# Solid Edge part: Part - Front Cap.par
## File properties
Author: hhakima
Template: Normal.par
Last saved by: hhakima
Revision: 21
Application: Solid Edge
Density: 2712.000 kg/m^3
Accuracy: 0.990
Material: Aluminum, 6061-T6
Face Style: Aluminum
Fill Style: ANSI38(Aluminum)
Virtual Style: Polished aluminum
Coef. of Thermal Exp: 2.3e-05
Thermal Conductivity: 180.0
Specific Heat: 920.0
Modulus of Elasticity: 68947570000.0
Poission's Ratio: 0.33
Yield Stress: 275790280.0
Ultimate Stress: 310264065.0
Elongation: 0.0
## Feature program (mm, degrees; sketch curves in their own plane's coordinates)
sketch for "unnamed Protrusion 1" plane through (0, 0, 0) normal (0, -1, 0) x-axis (1, 0, 0)
  line (42.2517, 30.6615) -> (98.2517, 30.6615)
  line (98.2517, 30.6615) -> (98.2517, 67.6615)
  line (98.2517, 67.6615) -> (42.2517, 67.6615)
  line (42.2517, 67.6615) -> (42.2517, 30.6615)
extrude "unnamed Protrusion 1" add finite 2 along +normal
sketch for "ExtrudedProtrusion_2" #1 plane through (63.7517, -2, 49.1615) normal (0, -1, 0) x-axis (1, 0, 0)
  line (-21.5, -13.5) -> (-21.5, -18.5)
  line (-21.5, -18.5) -> (-26.5, -18.5)
  line (-26.5, -18.5) -> (-26.5, -13.5)
  line (-26.5, -13.5) -> (-21.5, -13.5)
sketch for "ExtrudedProtrusion_2" #2 plane through (63.7517, -2, 49.1615) normal (0, -1, 0) x-axis (1, 0, 0)
  line (34.5, -13.5) -> (34.5, -18.5)
  line (34.5, -18.5) -> (39.5, -18.5)
  line (39.5, -18.5) -> (39.5, -13.5)
  line (39.5, -13.5) -> (34.5, -13.5)
sketch for "ExtrudedProtrusion_2" #3 plane through (63.7517, -2, 49.1615) normal (0, -1, 0) x-axis (1, 0, 0)
sketch for "ExtrudedProtrusion_2" #4 plane through (63.7517, -2, 49.1615) normal (0, -1, 0) x-axis (1, 0, 0)
  line (24.5, 18.5) -> (29.5, 18.5)
  line (29.5, 18.5) -> (29.5, 23.5)
  line (29.5, 23.5) -> (24.5, 23.5)
  line (24.5, 23.5) -> (24.5, 18.5)
  dimension (linear) = 24.5
extrude "ExtrudedProtrusion_2" add finite 2 along -normal
sketch for "Hole_1" plane through (63.7517, -2, 49.1615) normal (0, -1, 0) x-axis (1, 0, 0)
  hole centre (27, 21) bore radius 1.1
hole "Hole_1" diameter 2.2 through
sketch for "unnamed Hole 1" plane through (63.7517, -2, 49.1615) normal (0, -1, 0) x-axis (1, 0, 0)
  hole centre (37, -16) bore radius 1.1
hole "unnamed Hole 1" through
sketch for "unnamed Hole 2" plane through (63.7517, -2, 49.1615) normal (0, -1, 0) x-axis (1, 0, 0)
  hole centre (-24, -16) bore radius 1.1
  dimension (linear) = 24
  dimension (linear) = 24
hole "unnamed Hole 2" through
sketch for "unnamed Hole 3" plane through (63.7517, -2, 49.1615) normal (0, -1, 0) x-axis (1, 0, 0)
hole "unnamed Hole 3" through
pattern "unnamed Pattern 1" of "Hole_1", "unnamed Hole 1", "unnamed Hole 2", "unnamed Hole 3"
sketch for "ExtrudedCutout_1" plane through (69.2517, -2, 49.1615) normal (0, -1, 0) x-axis (1, 0, 0)
  circle centre (-7.5, 4) radius 3.5
  dimension (linear) = 7.5
  dimension (linear) = 7.5
extrude "ExtrudedCutout_1" cut finite 5 along -normal
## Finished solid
Body 1: solid body, 23 faces, 58 edges, 32 vertices.
  Faces by surface: plane 18, cylinder 5
  Edges by curve: line 48, circle 10
Bounding box of the edges (mm): 66.000 x 2.000 x 42.000, from (37.2517, -2, 30.6615) to (103.2517, 0, 72.6615).
Cylindrical faces by radius (mm): R1.1 x4, R3.5 x1
Planar faces by outward normal: +x 4, +y 1, +z 7, -x 4, -y 1, -z 1
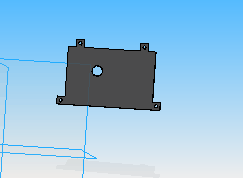
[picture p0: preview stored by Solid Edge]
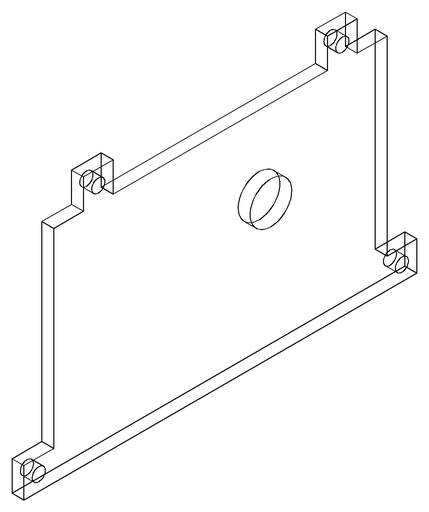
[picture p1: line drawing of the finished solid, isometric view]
